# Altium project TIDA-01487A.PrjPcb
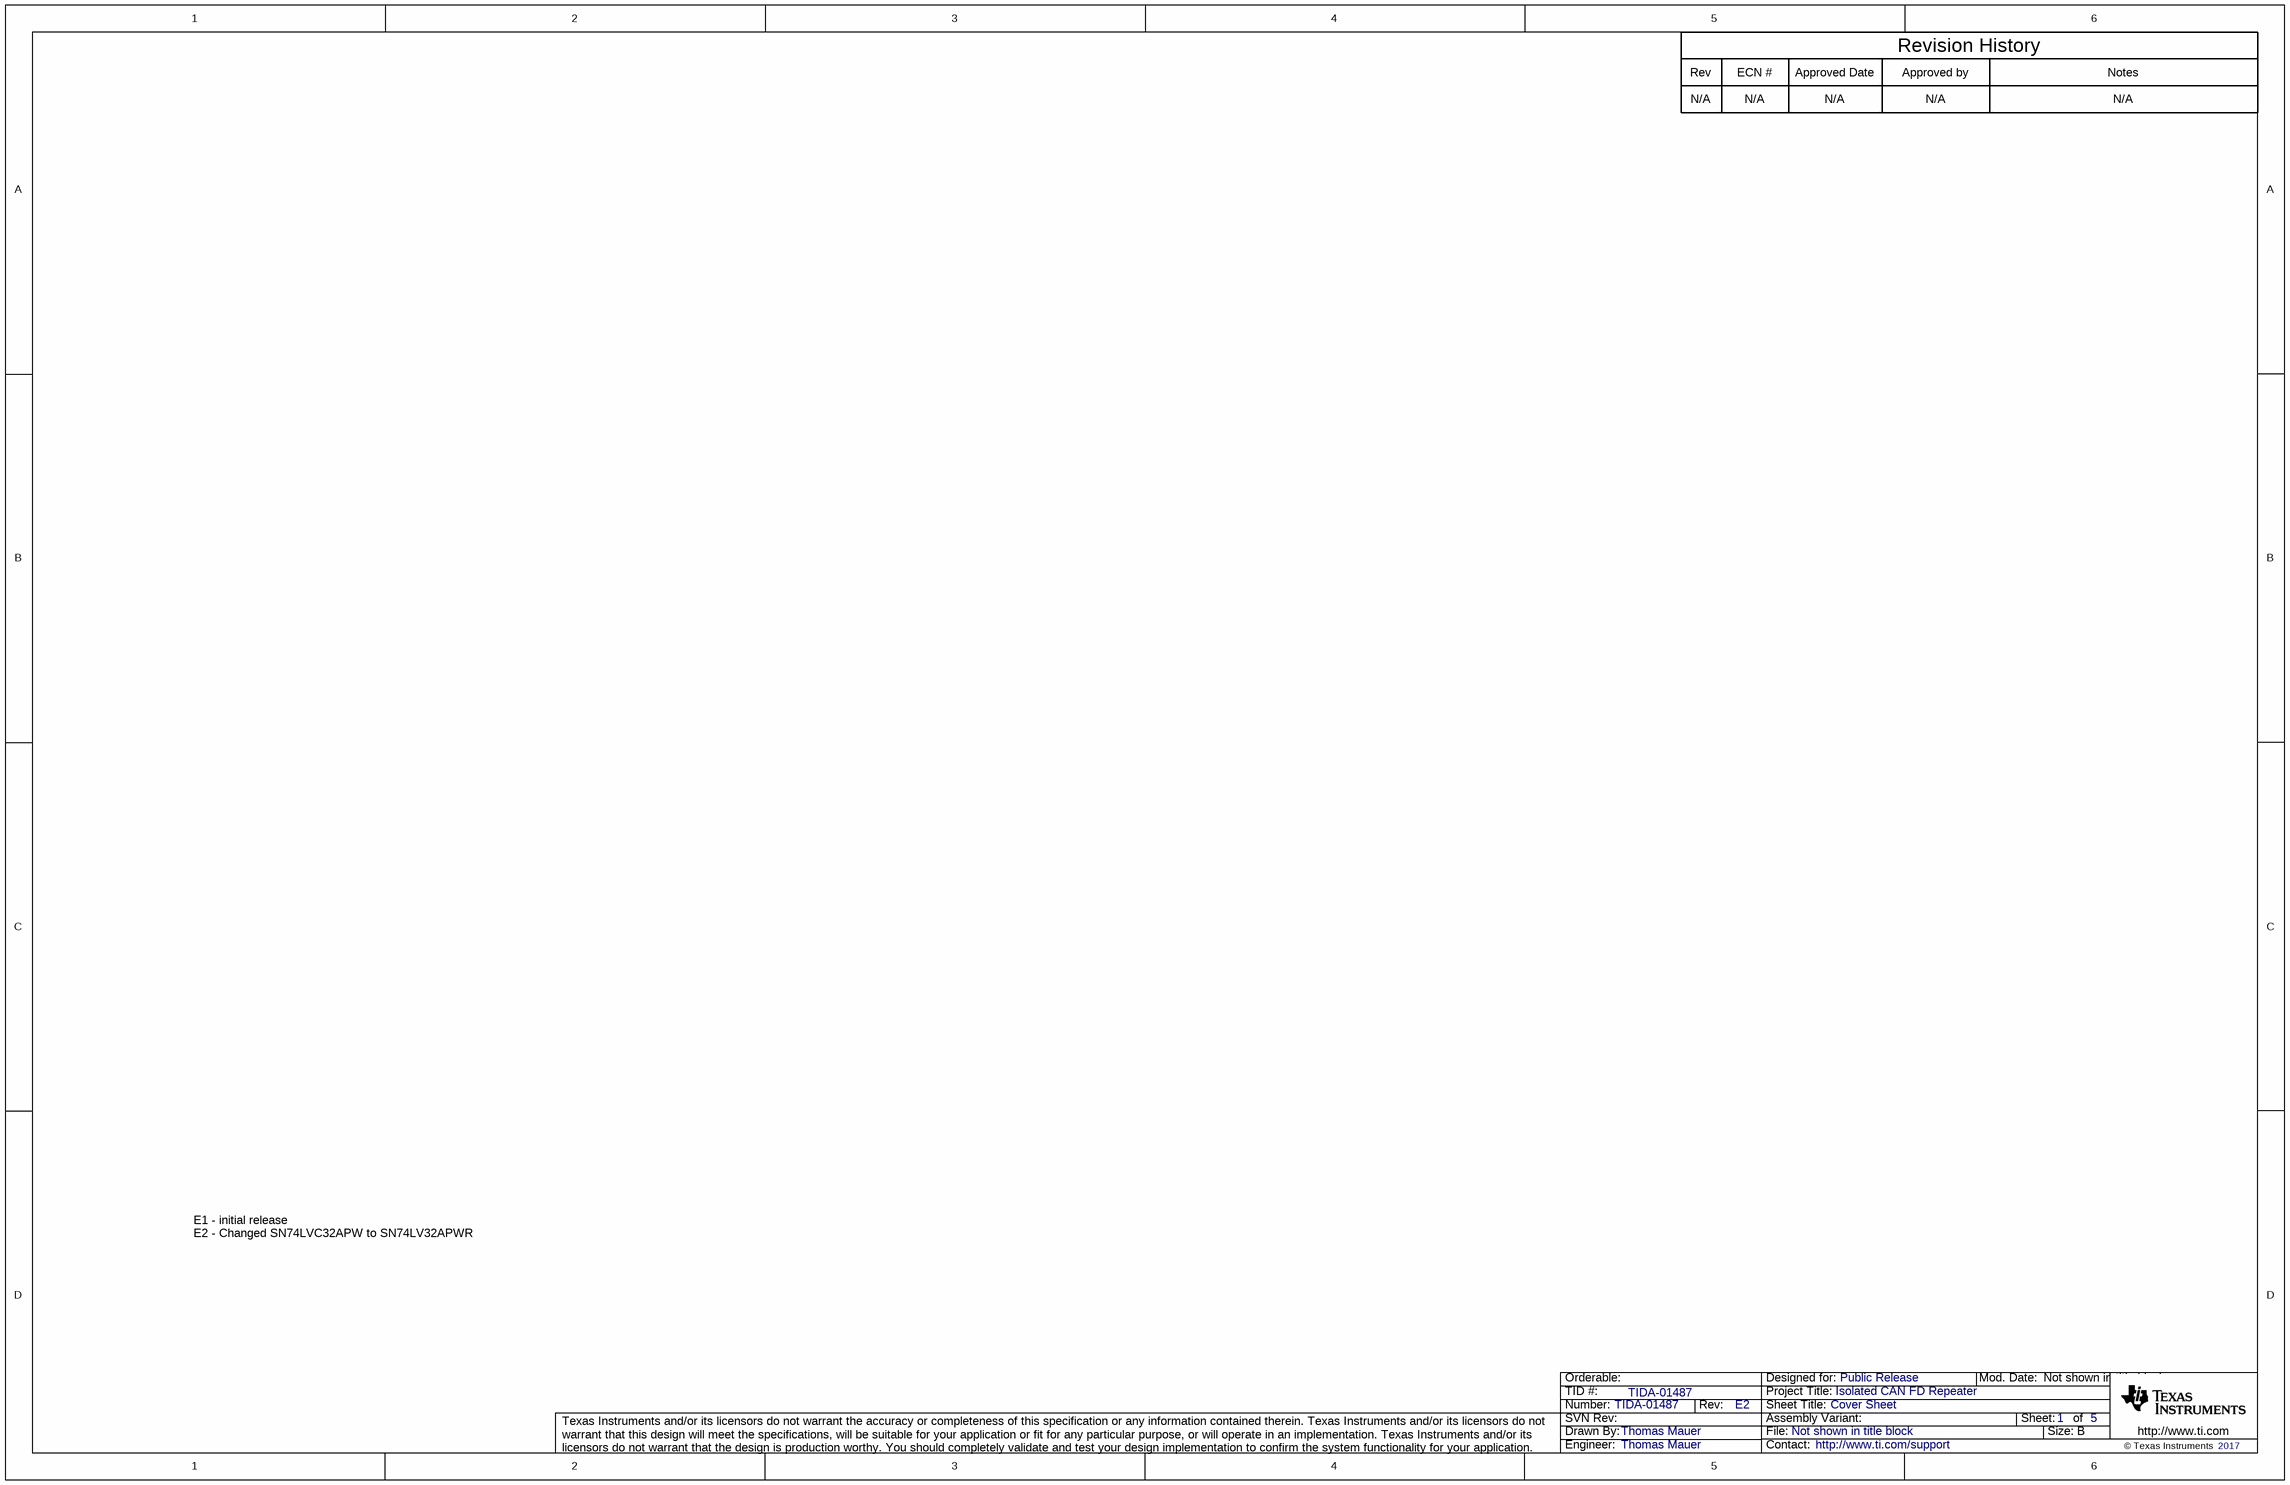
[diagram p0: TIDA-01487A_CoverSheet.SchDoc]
CopyrightYear: 2017; PCB_Layout: Thomas Mauer; PCB_Rev: E2; PRJ_Customer: Public Release; PRJ_Engineer: Thomas Mauer; PRJ_Number: TIDA-01487; PRJ_Title: Isolated CAN FD Repeater; SCH_Rev: E2; TechSupport: http://www.ti.com/support; TID: TIDA-01487
5 sheets, 83 parts. Net scope: flat (ports and power ports of the same name join across sheets).
Board file: TIDA-01487A.PcbDoc
Sheets:
  TIDA-01487A_CoverSheet.SchDoc
  TIDA-01487A_Power.SchDoc
  TIDA-01487A_BusArbitrationLogic.SchDoc
  TIDA-01487A_CanFdInterface.SchDoc
  TIDA-01487A_EVM_Hardware.SchDoc

## Sheet TIDA-01487A_CoverSheet.SchDoc: Cover Sheet
size 431 x 279 mm; Date: Not shown in title block; ApprovedBy: Not shown in title block; CheckedBy: Not shown in title block; Author: Not shown in title block; CompanyName: Not shown in title block; DrawnBy: Thomas Mauer; Engineer: Not shown in title block; Organization: Not shown in title block; Address1: Not shown in title block; Address2: Not shown in title block; Address3: Not shown in title block; Address4: Not shown in title block; DocumentNumber: 1; Revision: Use project parameter SCH_Rev; SheetNumber: 1; SheetTotal: 5; PageSetup: Record=PageOptions¦CenterHorizontal=True¦CenterVertical=True¦PrintScale=1.00¦XCorrection=1.00¦YCorrection=1.00¦PrintKind=0¦BorderSize=5000000¦LeftOffset=0¦BottomOffset=0¦Orientation=2¦PaperLength=1000¦PaperWidth=1000¦Scale=100¦PaperSource=15¦PrintQuality=600¦MediaType=1¦DitherType=10¦PaperKind=Letter¦PrintScaleMode=1

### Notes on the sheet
- Rev
- N/A
- ECN #
- Approved Date
- Approved by
- Revision History
- Notes
- E1 - initial release
  E2 - Changed SN74LVC32APW to SN74LV32APWR

## Sheet TIDA-01487A_Power.SchDoc: Power Supply
size 431 x 279 mm; Date: Not shown in title block; ApprovedBy: Not shown in title block; CheckedBy: Not shown in title block; Author: Not shown in title block; CompanyName: Not shown in title block; DrawnBy: Thomas Mauer; Engineer: Not shown in title block; Organization: Not shown in title block; Address1: Not shown in title block; Address2: Not shown in title block; Address3: Not shown in title block; Address4: Not shown in title block; DocumentNumber: 1; Revision: Use project parameter SCH_Rev; SheetNumber: 2; SheetTotal: 5; PageSetup: Record=PageOptions¦CenterHorizontal=True¦CenterVertical=True¦PrintScale=0.62¦XCorrection=1.00¦YCorrection=1.00¦PrintKind=0¦BorderSize=5000000¦LeftOffset=0¦BottomOffset=0¦Orientation=2¦PaperLength=1000¦PaperWidth=1000¦Scale=100¦PaperSource=15¦PrintQuality=600¦MediaType=1¦DitherType=10¦PrintScaleMode=1¦PaperKind=Letter
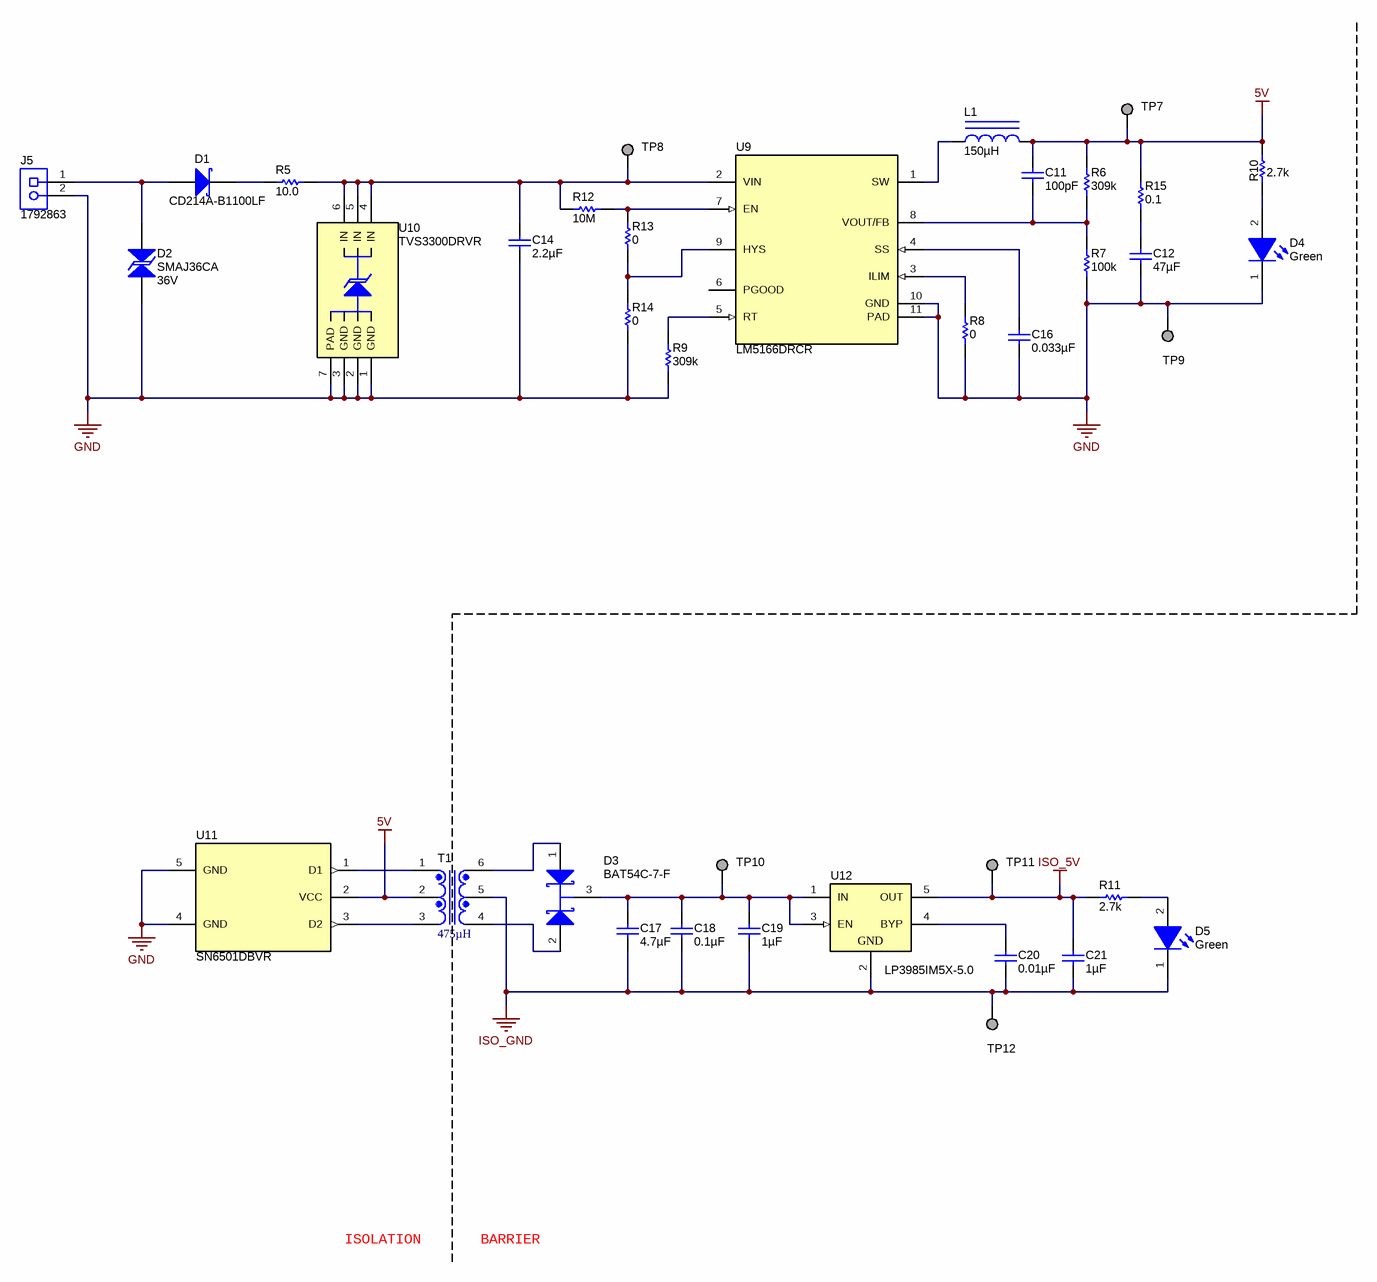
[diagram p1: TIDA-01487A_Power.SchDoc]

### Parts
C11  ValueDisplayed: 100pF  [0805_HV]  (hidden comment: GRM2165C1H101JA01D)
C12  ValueDisplayed: 47µF  [1210_270]  (hidden comment: GCM32ER70J476KE19L)
C14  ValueDisplayed: 2.2µF  [1210_270]  (hidden comment: GRM32ER72A225KA35L)
C16  ValueDisplayed: 0.033µF  [0603]  (hidden comment: GRM188R71H333KA61D)
C17  ValueDisplayed: 4.7µF  [1210_270]  (hidden comment: GRM32ER71K475KE14L)
C18  ValueDisplayed: 0.1µF  [0805_HV]  (hidden comment: ECPU1C104MA5)
C19  ValueDisplayed: 1µF  [0805_HV]  (hidden comment: EMK212B7105KG-T)
C20  ValueDisplayed: 0.01µF  [0805_HV]  (hidden comment: GRM216R71H103KA01D)
C21  ValueDisplayed: 1µF  [0805_HV]  (hidden comment: EMK212B7105KG-T)
D1  CD214A-B1100LF  [SMA]
D2  SMAJ36CA  value 36V  [SMA]
D3  BAT54C-7-F  [SOT-23]
D4  value Green  [WL-SMCW_Green_0805]  (hidden comment: 150080GS75000)
D5  value Green  [WL-SMCW_Green_0805]  (hidden comment: 150080GS75000)
J5  1792863  [Phoenix_1792863]
L1  ValueDisplayed: 150µH  [WE-PD_1050]  (hidden comment: 7447714151)
R5  ValueDisplayed: 10.0  [1206]  (hidden comment: ERJ-8ENF10R0V)
R6  ValueDisplayed: 309k  [0805_HV]  (hidden comment: CRCW0805309KFKEA)
R7  ValueDisplayed: 100k  [0805_HV]  (hidden comment: CRCW0805100KFKEA)
R8  ValueDisplayed: 0  [0805_HV]  (hidden comment: CRCW08050000Z0EA)
R9  ValueDisplayed: 309k  [0805_HV]  (hidden comment: CRCW0805309KFKEA)
R10  ValueDisplayed: 2.7k  [0805_HV]  (hidden comment: CRCW08052K70JNEA)
R11  ValueDisplayed: 2.7k  [0805_HV]  (hidden comment: CRCW08052K70JNEA)
R12  ValueDisplayed: 10M  [0805_HV]  (hidden comment: CRCW080510M0JNEA)
R13  ValueDisplayed: 0  [0805_HV]  (hidden comment: CRCW08050000Z0EA)
R14  ValueDisplayed: 0  [0805_HV]  (hidden comment: CRCW08050000Z0EA)
R15  ValueDisplayed: 0.1  [0805_HV]  (hidden comment: CRM0805-FX-R100ELF)
T1  ValueDisplayed: 475µH  [Wurth_760390013]  (hidden comment: 760390014)
TP7  TESTPOINT  [TESTPOINT]  (value not drawn)  (no BOM)
TP8  TESTPOINT  [TESTPOINT]  (value not drawn)  (no BOM)
TP9  TESTPOINT  [TESTPOINT]  (value not drawn)  (no BOM)
TP10  TESTPOINT  [TESTPOINT]  (value not drawn)  (no BOM)
TP11  TESTPOINT  [TESTPOINT]  (value not drawn)  (no BOM)
TP12  TESTPOINT  [TESTPOINT]  (value not drawn)  (no BOM)
U9  LM5166DRCR  [DRC0010J]
U10  TVS3300DRVR  [DRV0006A]
U11  SN6501DBVR  [DBV0005A_N]
U12  LP3985IM5X-5.0  [MF05A_N]

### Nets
5V: C11.1 L1.2 R6.2 R10.2 R15.2 T1.2 TP7.1 U11.2(VCC)
GND: C12.2 C14.2 C16.2 D2.1 D4.1(K) J5.2 R7.1 R8.1 R9.1 R14.1 TP9.1 U9.10(GND) U9.11(PAD) U10.1(GND) U10.2(GND) U10.3(GND) U10.7(PAD) U11.4(GND) U11.5(GND)
ISO_5V: C21.1 R11.2 TP11.1 U12.5(OUT)
ISO_GND: C17.2 C18.2 C19.2 C20.2 C21.2 D5.1(K) T1.5 TP12.1 U12.2(GND)
NetC11_2: C11.2 R6.1 R7.2 U9.8(VOUT/FB)
NetC12_1: C12.1 R15.1
NetC14_1: C14.1 R5.2 R12.1 TP8.1 U9.2(VIN) U10.4(IN) U10.5(IN) U10.6(IN)
NetC16_1: C16.1 U9.4(SS)
NetC17_1: C17.1 C18.1 C19.1 D3.3(K) TP10.1 U12.1(IN) U12.3(EN)
NetC20_1: C20.1 U12.4(BYP)
NetD1_1: D1.1(K) R5.1
NetD1_2: D1.2(A) D2.2 J5.1
NetD3_1: D3.1(A1) T1.6
NetD3_2: D3.2(A2) T1.4
NetD4_2: D4.2(A) R10.1
NetD5_2: D5.2(A) R11.1
NetL1_1: L1.1 U9.1(SW)
NetR8_2: R8.2 U9.3(ILIM)
NetR9_2: R9.2 U9.5(RT)
NetR12_2: R12.2 R13.2 U9.7(EN)
NetR13_1: R13.1 R14.2 U9.9(HYS)
NetT1_1: T1.1 U11.1(D1)
NetT1_3: T1.3 U11.3(D2)

Not connected (* = marked no-connect by the designer): U9 6(PGOOD)

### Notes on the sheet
- ISOLATION       BARRIER

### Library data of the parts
C11 = GRM2165C1H101JA01D: CAP, CERM, 100 pF, 50 V,+/- 5%, C0G/NP0, 0805; Manufacturer: MuRata; Polarized: N; CompType: Capacitor; Value: 100pF; U/M: EA; Cap_F: 0.0000000001; Tolerance_%: 5; VDC_V: 50; Value2: 50V; TaMin_C: -55; TaMax_C: 125; Cap_Case: 0805; SizeArea_mm2: 2.5; SizeAreaWB_mm2: 6.75; SizeX_mm: 2; SizeY_mm: 1.25; SizeZ_mm: 1.45; AEC Category: Q200; Green_Lifecycle: Active; Green_REACh: Passed
C12 = GCM32ER70J476KE19L: CAP, CERM, 47 µF, 6.3 V,+/- 10%, X7R, AEC-Q200 Grade 1, 1210; Manufacturer: MuRata; Polarized: N; CompType: Capacitor; Value: 47uF; U/M: EA; Cap_F: 0.000047; Tolerance_%: 10; VDC_V: 6.3; Value2: 6.3V; TaMin_C: -55; TaMax_C: 125; Cap_Case: 1210; SizeArea_mm2: 8; SizeAreaWB_mm2: 14.7; SizeX_mm: 3.2; SizeY_mm: 2.5; SizeZ_mm: 2.7; AEC Category: Q200; AEC Qualified: Y; AEC Grade: 1; Green_Lifecycle: Active; Green_REACh: Passed
C14 = GRM32ER72A225KA35L: CAP, CERM, 2.2 µF, 100 V,+/- 10%, X7R, 1210; Manufacturer: MuRata; Polarized: N; CompType: Capacitor; Value: 2.2uF; U/M: EA; Cap_F: 0.0000022; Tolerance_%: 10; ESR_ohm: 0.007; Value1: 0.007 ohm; VDC_V: 100; Value2: 100V; IRMS_A: 4.4; TaMin_C: -55; TaMax_C: 125; Cap_Case: 1210; SizeArea_mm2: 8; SizeAreaWB_mm2: 14.7; SizeX_mm: 3.2; SizeY_mm: 2.5; SizeZ_mm: 2.7; AEC Category: Q200; Green_Lifecycle: Active; Green_REACh: Passed
C16 = GRM188R71H333KA61D: CAP, CERM, 0.033 µF, 50 V,+/- 10%, X7R, 0603; Manufacturer: MuRata; Polarized: N; CompType: Capacitor; Value: 0.033uF; U/M: EA; Cap_F: 0.000000033; Tolerance_%: 10; VDC_V: 50; Value2: 50V; TaMin_C: -55; TaMax_C: 125; SizeArea_mm2: 1.28; SizeAreaWB_mm2: 4.68; SizeX_mm: 1.6; SizeY_mm: 0.8; SizeZ_mm: 1; AEC Category: Q200; Green_Lifecycle: Active; Green_REACh: Passed
C17 = GRM32ER71K475KE14L: CAP, CERM, 4.7 µF, 80 V,+/- 10%, X7R, 1210; Manufacturer: MuRata; Polarized: N; CompType: Capacitor; Value: 4.7uF; U/M: EA; Cap_F: 0.0000047; Tolerance_%: 10; VDC_V: 80; Value2: 80V; TaMin_C: -55; TaMax_C: 125; Cap_Case: 1210; SizeArea_mm2: 8; SizeAreaWB_mm2: 14.7; SizeX_mm: 3.2; SizeY_mm: 2.5; SizeZ_mm: 2.7; AEC Category: Q200
C18 = ECPU1C104MA5: CAP, Film, 0.1 µF, 16 V,+/- 20%, 0805 SMD; Manufacturer: Panasonic; Polarized: N; CompType: Capacitor; Value: 0.1uF; U/M: EA; Cap_F: 0.0000001; Tolerance_%: 20; VDC_V: 16; Value2: 16V; TaMin_C: -40; TaMax_C: 85; Cap_Case: 0805; SizeAreaWB_mm2: 6.75; SizeArea_mm2: 2.5; SizeX_mm: 2; SizeY_mm: 1.25; SizeZ_mm: 1.45; AEC Category: Q200
C19 C21 = EMK212B7105KG-T: CAP, CERM, 1 µF, 16 V,+/- 10%, X7R, 0805; Manufacturer: Taiyo Yuden; Polarized: N; CompType: Capacitor; Value: 1uF; U/M: EA; Cap_F: 0.000001; Tolerance_%: 10; VDC_V: 16; Value2: 16V; TaMin_C: -55; TaMax_C: 125; Cap_Case: 0805; SizeArea_mm2: 2.5; SizeAreaWB_mm2: 6.75; SizeX_mm: 2; SizeY_mm: 1.25; SizeZ_mm: 1.45; AEC Category: Q200; Green_Lifecycle: Active; Green_REACh: Passed
C20 = GRM216R71H103KA01D: CAP, CERM, 0.01 µF, 50 V,+/- 10%, X7R, 0805; Manufacturer: MuRata; Polarized: N; CompType: Capacitor; Value: 0.01uF; U/M: EA; Cap_F: 0.00000001; Tolerance_%: 10; VDC_V: 50; Value2: 50V; TaMin_C: -55; TaMax_C: 125; Cap_Case: 0805; SizeArea_mm2: 2.5; SizeAreaWB_mm2: 6.75; SizeX_mm: 2; SizeY_mm: 1.25; SizeZ_mm: 1.45; AEC Category: Q200; Green_Lifecycle: Active; Green_REACh: Passed
D1 = CD214A-B1100LF: Diode, Schottky, 100 V, 1 A, SMA; Manufacturer: Bourns; U/M: EA; Vf_V: 0.79; Value: 100V; Value1: 1A; Value2: 0.79V; Io_A: 1; Vr_V: 100; TJmax_C: 125; RJC_CperW: 25; SizeAreaWB_mm2: 37.3428; SizeArea_mm2: 16.3228; SizeX_mm: 5.59; SizeY_mm: 2.92; SizeZ_mm: 2.87; AEC Category: Q101; Green_Lifecycle: Not Set; Green_REACh: Incomplete
D2 = SMAJ36CA: Diode, TVS, Bi, 36 V, SMA; Manufacturer: Littelfuse; U/M: EA; Power_W: 3.3; Vr_V: 36; Value1: 3.3W; RJA_CperW: 120; SizeAreaWB_mm2: 37.3428; SizeArea_mm2: 16.3228; SizeX_mm: 5.59; SizeY_mm: 2.92; SizeZ_mm: 2.87; AEC Category: Q101
D3 = BAT54C-7-F: Diode, Schottky, 30 V, 0.2 A, SOT-23; Manufacturer: Diodes Inc.; Value: 30V; U/M: EA; Vf_V: 0.65; Value1: 0.2A; Value2: 0.65V; Io_A: 0.2; Vr_V: 30; TJmax_C: 125; SizeAreaWB_mm2: 14; SizeArea_mm2: 7.5; SizeX_mm: 2.5; SizeY_mm: 3; SizeZ_mm: 1.1; AEC Category: Q101; Green_Lifecycle: Active; Green_REACh: Passed
D4 D5 = 150080GS75000: LED, Green, SMD; Manufacturer: Wurth Elektronik; Type: InGaN; Vf_V: 3.2; Value2: 3.2V; Io_A: 0.02; Vr_V: 5; Ir_A: 1e-005; Tjmax_C: 85; Power_TotalModule: 0.105; Value1: 0.105W; Angle: 140; U/M: EA
J5 = 1792863: Terminal Block, 5mm, 2x1, R/A, TH; Manufacturer: Phoenix Contact; SymbolCreator: a0412235; Pitch_mm: 5; Gender: Female; Row_Count: 1; Current_A: 16; Voltage_V: 400; Cert_UL: Y
L1 = 7447714151: Inductor, Shielded Drum Core, Ferrite, 150 µH, 1.2 A, 0.251 ohm, SMD; Manufacturer: Wurth Elektronik; Value: 150uH; Ind_H: 150.0E-6; Imax_A: 1.2; Irms: 1.2A @ 40C rise; Isat: 1.4A @ 10% inductance drop; DCR_ohm: 0.251; Value2: 1.2A; SizeAreaWB_mm2: 144; SizeArea_mm2: 100; SizeX_mm: 10; SizeZ_mm: 5; AEC Category: Q200; Green_Lifecycle: Active; Green_REACh: Passed
R5 = ERJ-8ENF10R0V: RES, 10.0, 1%, 0.25 W, 1206; Manufacturer: Panasonic; CompType: Resistor; Value: 10.0; Res_ohm: 10; Value_Code: 10R0; Tolerance_%: 1; Power_W: 0.25; Value2: 0.25W; VDC_V: 200; TempCo: 100 ppm/C; SizeArea_mm2: 5.12; SizeX_mm: 3.2; SizeY_mm: 1.6; SizeZ_mm: 1.35; EIA_Code: E96; U/M: EA; AEC Category: Q200; Green_Lifecycle: Active; Green_REACh: Passed
R6 R9 = CRCW0805309KFKEA: RES, 309 k, 1%, 0.125 W, 0805; Manufacturer: Vishay-Dale; CompType: Resistor; Value: 309k; Res_ohm: 309000; Tolerance_%: 1; Power_W: 0.125; Value2: 0.125W; VDC_V: 150; TempCo: 100 ppm/C; SizeArea_mm2: 2.5; SizeX_mm: 2; SizeY_mm: 1.25; SizeZ_mm: 1.45; EIA_Code: E96; U/M: EA; AEC Category: Q200
R7 = CRCW0805100KFKEA: RES, 100 k, 1%, 0.125 W, 0805; Manufacturer: Vishay-Dale; CompType: Resistor; Value: 100k; Res_ohm: 100000; Tolerance_%: 1; Power_W: 0.125; Value2: 0.125W; VDC_V: 150; TempCo: 100 ppm/C; SizeArea_mm2: 2.5; SizeX_mm: 2; SizeY_mm: 1.25; SizeZ_mm: 1.45; EIA_Code: E96; U/M: EA; AEC Category: Q200; Green_Lifecycle: Active; Green_REACh: Passed
R8 R13 R14 = CRCW08050000Z0EA: RES, 0, 5%, 0.125 W, 0805; Manufacturer: Vishay-Dale; CompType: Resistor; Value: 0; Value_Code: 0000; Tolerance_%: 5; Power_W: 0.125; Value2: 0.125W; VDC_V: 150; TempCo: 200 ppm/C; SizeArea_mm2: 2.5; SizeX_mm: 2; SizeY_mm: 1.25; SizeZ_mm: 1.45; EIA_Code: E24; U/M: EA; AEC Category: Q200; Green_Lifecycle: Active; Green_REACh: Passed
R10 R11 = CRCW08052K70JNEA: RES, 2.7 k, 5%, 0.125 W, 0805; Manufacturer: Vishay-Dale; CompType: Resistor; Value: 2.7k; Res_ohm: 2700; Value_Code: 2k70; Tolerance_%: 5; Power_W: 0.125; Value2: 0.125W; VDC_V: 150; TempCo: 200 ppm/C; SizeArea_mm2: 2.5; SizeX_mm: 2; SizeY_mm: 1.25; SizeZ_mm: 1.45; EIA_Code: E24; U/M: EA; AEC Category: Q200
R12 = CRCW080510M0JNEA: RES, 10 M, 5%, 0.125 W, 0805; Manufacturer: Vishay-Dale; CompType: Resistor; Value: 10Meg; Res_ohm: 10000000; Value_Code: 10M0; Tolerance_%: 5; Power_W: 0.125; Value2: 0.125W; VDC_V: 150; TempCo: 200 ppm/C; SizeArea_mm2: 2.5; SizeX_mm: 2; SizeY_mm: 1.25; SizeZ_mm: 1.45; EIA_Code: E24; U/M: EA; AEC Category: Q200
R15 = CRM0805-FX-R100ELF: RES, 0.1, 1%, 0.25 W, 0805; Manufacturer: Bourns; CompType: Resistor; Value: 0.1; Value_Code: R100; Tolerance_%: 1; Power_W: 0.25; Value2: 0.25W; VDC_V: 0; TempCo: 150 ppm/C; SizeArea_mm2: 2.5; SizeX_mm: 2; SizeY_mm: 1.25; SizeZ_mm: 1.45; EIA_Code: E96; U/M: EA; AEC Category: Q200; Green_Lifecycle: Active; Green_REACh: Passed
T1 = 760390014: Transformer, 475uH, SMT; Manufacturer: Wurth Elektronik; SymbolCreator: a0799628; DCR_ohm: 0.31; Lp: 475; Ind_H: 0.000475
TP7-TP12 = TESTPOINT: TEST POINT.  No entry in BOM.
U9 = LM5166DRCR: 3V-65V Input, 500mA Synchronous Buck Converter With Ultra-Low Iq, DRC0010J (VSON-10); Alternate PartNumber: LM5166DRCT; Manufacturer: Texas Instruments; SymbolCreator: a0411947; SizeArea_mm2: 9; SizeAreaWB_mm2: 16; SizeX_mm: 3; SizeZ_mm: 1; CompType: IC; U/M: EA
U10 = TVS3300DRVR: 33V Precision Surge Protection Clamp, DRV0006A (WSON-6); Alternate PartNumber: TVS3300DRVT; Manufacturer: Texas Instruments; SymbolCreator: Altium; SizeArea_mm2: 4; SizeAreaWB_mm2: 9; SizeX_mm: 2; SizeZ_mm: 0.8; CompType: IC; U/M: EA
U11 = SN6501DBVR: Low-Noise 350 mA, 410 kHz Transformer Driver, DBV0005A (SOT-23-5); Alternate PartNumber: SN6501DBVT; Manufacturer: Texas Instruments; SymbolCreator: a0411947; SizeArea_mm2: 8.12; SizeAreaWB_mm2: 14.82; SizeX_mm: 2.8; SizeY_mm: 2.9; SizeZ_mm: 1.45; CompType: IC; U/M: EA; Green_Lifecycle: Not Set; Green_REACh: Passed
U12 = LP3985IM5X-5.0: Micropower, 150mA Low-Noise Ultra Low-Dropout CMOS Voltage Regulator, 5-pin SOT-23; Manufacturer: Texas Instruments; PackageTopMarking: LDSB*XTT; PowerWise: N; CompType: LDO IC

## Sheet TIDA-01487A_BusArbitrationLogic.SchDoc: Bus Arbitration Logic
size 431 x 279 mm; Date: Not shown in title block; ApprovedBy: Not shown in title block; CheckedBy: Not shown in title block; Author: Not shown in title block; CompanyName: Not shown in title block; DrawnBy: Thomas Mauer; Engineer: Not shown in title block; Organization: Not shown in title block; Address1: Not shown in title block; Address2: Not shown in title block; Address3: Not shown in title block; Address4: Not shown in title block; DocumentNumber: 1; Revision: Use project parameter SCH_Rev; SheetNumber: 3; SheetTotal: 5; PageSetup: Record=PageOptions¦CenterHorizontal=True¦CenterVertical=True¦PrintScale=0.62¦XCorrection=1.00¦YCorrection=1.00¦PrintKind=0¦BorderSize=5000000¦LeftOffset=0¦BottomOffset=0¦Orientation=2¦PaperLength=1000¦PaperWidth=1000¦Scale=100¦PaperSource=15¦PrintQuality=600¦MediaType=1¦DitherType=10¦PrintScaleMode=1¦PaperKind=Letter
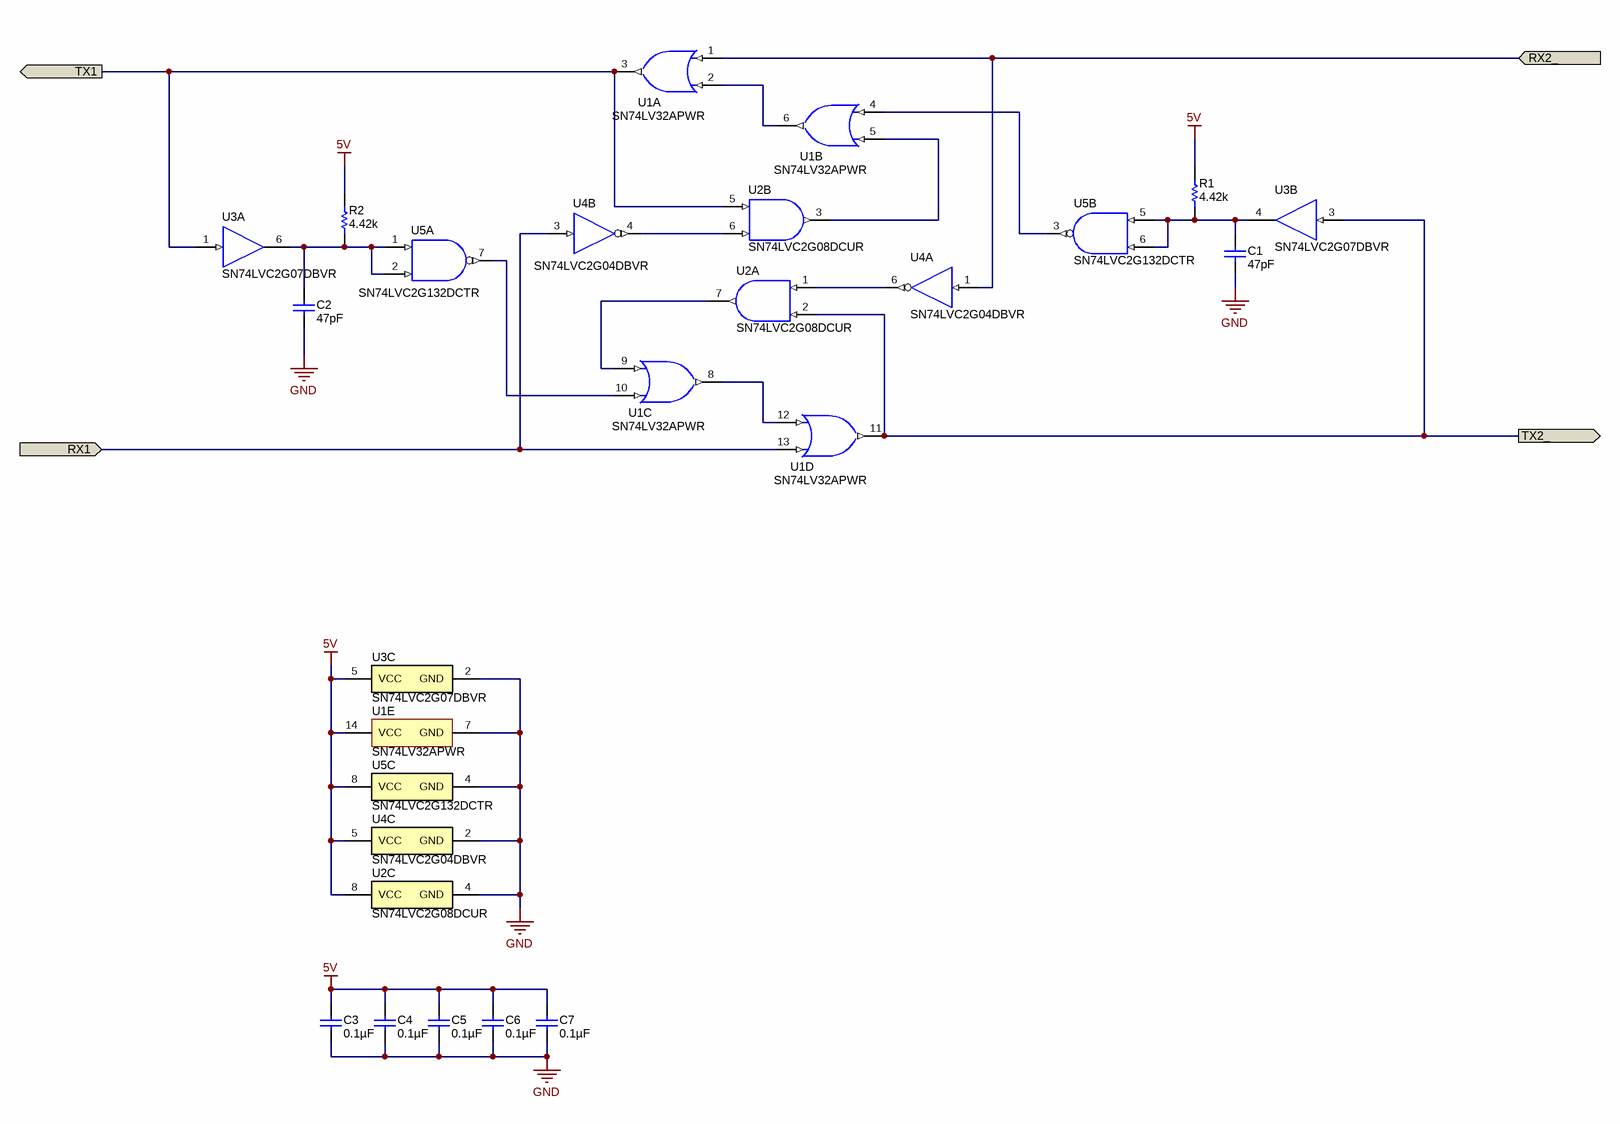
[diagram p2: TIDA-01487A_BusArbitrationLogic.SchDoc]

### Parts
C1  ValueDisplayed: 47pF  [0805_HV]  (hidden comment: GQM2195C1H470JB01D)
C2  ValueDisplayed: 47pF  [0805_HV]  (hidden comment: GQM2195C1H470JB01D)
C3  ValueDisplayed: 0.1µF  [0805_HV]  (hidden comment: ECPU1C104MA5)
C4  ValueDisplayed: 0.1µF  [0805_HV]  (hidden comment: ECPU1C104MA5)
C5  ValueDisplayed: 0.1µF  [0805_HV]  (hidden comment: ECPU1C104MA5)
C6  ValueDisplayed: 0.1µF  [0805_HV]  (hidden comment: ECPU1C104MA5)
C7  ValueDisplayed: 0.1µF  [0805_HV]  (hidden comment: ECPU1C104MA5)
R1  ValueDisplayed: 4.42k  [0805_HV]  (hidden comment: CRCW08054K42FKEA)
R2  ValueDisplayed: 4.42k  [0805_HV]  (hidden comment: CRCW08054K42FKEA)
U1  SN74LV32APWR  [PW0014A_N]  (parts A,B,C,D,E of 5)
U2  SN74LVC2G08DCUR  [DCU0008A_N]  (parts A,B,C of 3)
U3  SN74LVC2G07DBVR  [DBV0006A_N]  (parts A,B,C of 3)
U4  SN74LVC2G04DBVR  [DBV0006A_N]  (parts A,B,C of 3)
U5  SN74LVC2G132DCTR  [DCT0008A_N]  (parts A,B,C of 3)

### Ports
RX1 (in), RX2_ (in), TX1 (out), TX2_ (out)

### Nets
5V: C3.1 C4.1 C5.1 C6.1 C7.1 R1.2 R2.2 U1.14(VCC) U2.8(VCC) U3.5(VCC) U4.5(VCC) U5.8(VCC)
GND: C1.1 C2.1 C3.2 C4.2 C5.2 C6.2 C7.2 U1.7(GND) U2.4(GND) U3.2(GND) U4.2(GND) U5.4(GND)
RX1: U1.13(4B) U4.3(2A) ; port RX1
RX2_: U1.1(1A) U4.1(1A) ; port RX2_
TX1: U1.3(1Y) U2.5(2A) U3.1(1A) ; port TX1
TX2_: U1.11(4Y) U2.2(1B) U3.3(2A) ; port TX2_
NetC1_2: C1.2 R1.1 U3.4(2Y) U5.5(2A) U5.6(2B)
NetC2_2: C2.2 R2.1 U3.6(1Y) U5.1(1A) U5.2(1B)
NetU1_2: U1.2(1B) U1.6(2Y)
NetU1_4: U1.4(2A) U5.3(2Y)
NetU1_5: U1.5(2B) U2.3(2Y)
NetU1_8: U1.8(3Y) U1.12(4A)
NetU1_9: U1.9(3A) U2.7(1Y)
NetU1_10: U1.10(3B) U5.7(1Y)
NetU2_1: U2.1(1A) U4.6(1Y)
NetU2_6: U2.6(2B) U4.4(2Y)

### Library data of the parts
C1 C2 = GQM2195C1H470JB01D: CAP, CERM, 47 pF, 50 V,+/- 5%, C0G/NP0, 0805; Manufacturer: MuRata; Polarized: N; CompType: Capacitor; Value: 47pF; U/M: EA; Cap_F: 0.000000000047; Tolerance_%: 5; VDC_V: 50; Value2: 50V; TaMin_C: -55; TaMax_C: 125; Cap_Case: 0805; SizeArea_mm2: 2.5; SizeAreaWB_mm2: 6.75; SizeX_mm: 2; SizeY_mm: 1.25; SizeZ_mm: 1.45; AEC Category: Q200
C3-C7 = ECPU1C104MA5: as C18 on sheet TIDA-01487A_Power
R1 R2 = CRCW08054K42FKEA: RES, 4.42 k, 1%, 0.125 W, 0805; Manufacturer: Vishay-Dale; CompType: Resistor; Value: 4.42k; Res_ohm: 4420; Value_Code: 4k42; Tolerance_%: 1; Power_W: 0.125; Value2: 0.125W; VDC_V: 150; TempCo: 100 ppm/C; SizeArea_mm2: 2.5; SizeX_mm: 2; SizeY_mm: 1.25; SizeZ_mm: 1.45; EIA_Code: E96; U/M: EA; AEC Category: Q200
U1 = CMP-0050867-1: Quadruple 2-Input Positive-OR Gates, PW0014A, LARGE T&R; Manufacturer: Texas Instruments; ICC @ Nom Voltage(Max)(mA): 0.02; Input Type: TTL; VCC(Max)(V): 5.5; VCC(Min)(V): 2; F @ Nom Voltage(Max)(Mhz): 70; Rating: Catalog; Output Drive (IOL/IOH)(Max)(mA): 50/-50; Bits(#): 4; Voltage(Nom)(V): 2.5,3.3,5; tpd @ Nom Voltage(Max)(ns): 19,13,8.5
U2 = SN74LVC2G08DCUR: Dual 2-Input Positive-AND Gate, DCU0008A, LARGE T&R; Manufacturer: Texas Instruments; Alternate PartNumber: Equivalent; VCC(Min)(V): 1.65; VCC(Max)(V): 5.5; Output Type: CMOS; ICC @ Nom Voltage(Max)(mA): 0.01; Input Type: CMOS/TTL; Bits(#): 2; F @ Nom Voltage(Max)(Mhz): 150; Rating: Catalog; Technology Family: LVC; Voltage(Nom)(V): 1.8,2.5,3.3,5; Schmitt Trigger: No; Output Drive (IOL/IOH)(Max)(mA): 32/-32; tpd @ Nom Voltage(Max)(ns): 9.8,5.8,5.3,4.8; Logic: True; Gate Type: AND
U3 = SN74LVC2G07DBVR: Dual Buffer/Driver with Open-Drain Output, DBV0006A, LARGE T&R; Manufacturer: Texas Instruments; Alternate PartNumber: Equivalent; VCC(Min)(V): 1.65; VCC(Max)(V): 5.5; Output Type: CMOS; ICC @ Nom Voltage(Max)(mA): 0.01; Input Type: CMOS/TTL; Bits(#): 2; F @ Nom Voltage(Max)(Mhz): 150; Rating: Catalog; Technology Family: LVC; Voltage(Nom)(V): 1.8,2.5,3.3,5; Schmitt Trigger: No; Output Drive (IOL/IOH)(Max)(mA): 32/-32; tpd @ Nom Voltage(Max)(ns): 8.6,4.4,3.7,2.9; Logic: True; Sub-Family: Inverting Buffer/Driver
U4 = SN74LVC2G04DBVR: Dual Inverter, DBV0006A, LARGE T&R; Manufacturer: Texas Instruments; Alternate PartNumber: Equivalent; VCC(Min)(V): 1.65; VCC(Max)(V): 5.5; Output Type: CMOS; ICC @ Nom Voltage(Max)(mA): 0.01; Input Type: CMOS/TTL; Bits(#): 2; F @ Nom Voltage(Max)(Mhz): 150; Rating: Catalog; Technology Family: LVC; Voltage(Nom)(V): 1.8,2.5,3.3,5; Schmitt Trigger: No; Output Drive (IOL/IOH)(Max)(mA): 32/-32; tpd @ Nom Voltage(Max)(ns): 8,4.9,4.6,3.7; Logic: Inverting; Sub-Family: Inverting Buffer/Driver
U5 = SN74LVC2G132DCTR: Dual 2-Input NAND Gate with Schmitt-Trigger Inputs, DCT0008A, LARGE T&R; Manufacturer: Texas Instruments; Alternate PartNumber: Equivalent; VCC(Min)(V): 1.65; VCC(Max)(V): 5.5; Output Type: CMOS; ICC @ Nom Voltage(Max)(mA): 0.01; Input Type: CMOS/TTL; Bits(#): 2; F @ Nom Voltage(Max)(Mhz): 150; Rating: Catalog; Technology Family: LVC; Voltage(Nom)(V): 1.8,2.5,3.3,5; Schmitt Trigger: Yes; Output Drive (IOL/IOH)(Max)(mA): 32/-32; tpd @ Nom Voltage(Max)(ns): 16,7.5,6,5; Logic: True; 3-State Output: No

## Sheet TIDA-01487A_CanFdInterface.SchDoc: Bus Arbitration Logic
size 431 x 279 mm; Date: Not shown in title block; ApprovedBy: Not shown in title block; CheckedBy: Not shown in title block; Author: Not shown in title block; CompanyName: Not shown in title block; DrawnBy: Thomas Mauer; Engineer: Not shown in title block; Organization: Not shown in title block; Address1: Not shown in title block; Address2: Not shown in title block; Address3: Not shown in title block; Address4: Not shown in title block; DocumentNumber: 1; Revision: Use project parameter SCH_Rev; SheetNumber: 4; SheetTotal: 5; PageSetup: Record=PageOptions¦CenterHorizontal=True¦CenterVertical=True¦PrintScale=0.62¦XCorrection=1.00¦YCorrection=1.00¦PrintKind=0¦BorderSize=5000000¦LeftOffset=0¦BottomOffset=0¦Orientation=2¦PaperLength=1000¦PaperWidth=1000¦Scale=100¦PaperSource=15¦PrintQuality=600¦MediaType=1¦DitherType=10¦PrintScaleMode=1¦PaperKind=Letter
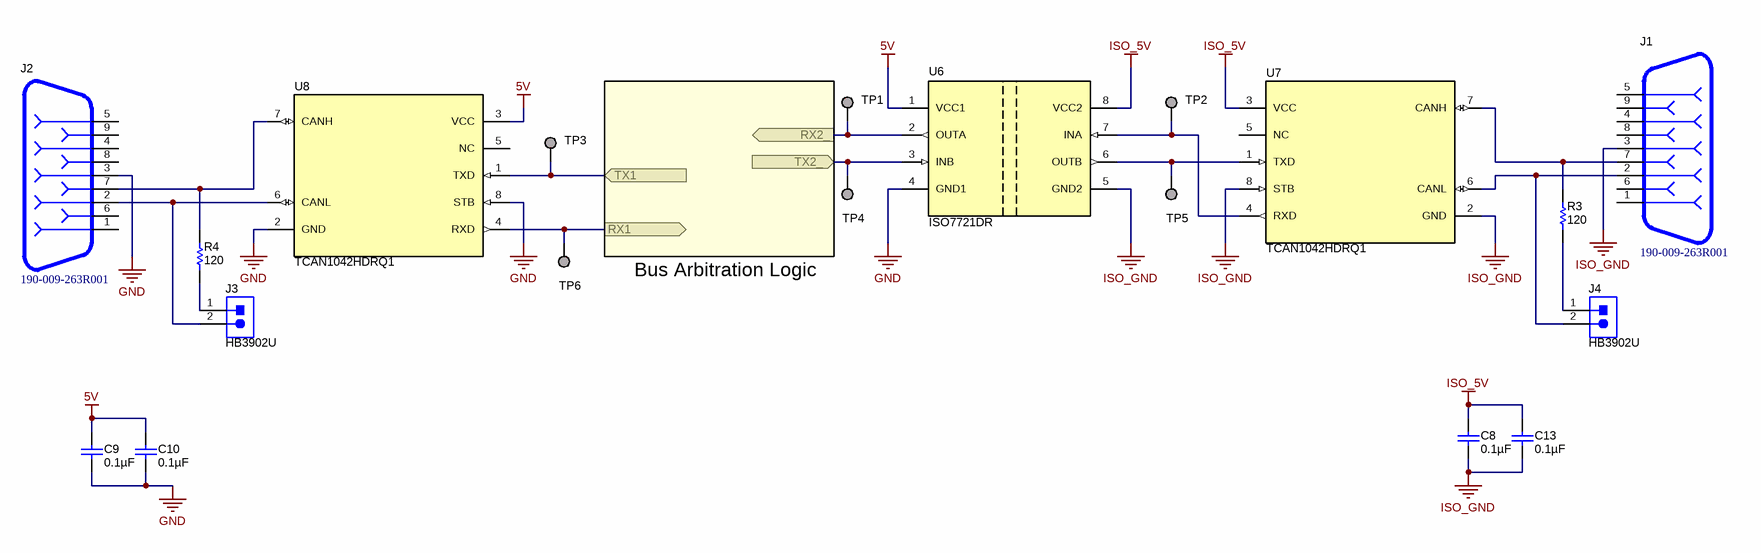
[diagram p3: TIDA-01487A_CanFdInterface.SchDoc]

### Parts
C8  ValueDisplayed: 0.1µF  [0805_HV]  (hidden comment: ECPU1C104MA5)
C9  ValueDisplayed: 0.1µF  [0805_HV]  (hidden comment: ECPU1C104MA5)
C10  ValueDisplayed: 0.1µF  [0805_HV]  (hidden comment: ECPU1C104MA5)
C13  ValueDisplayed: 0.1µF  [0805_HV]  (hidden comment: ECPU1C104MA5)
J1  190-009-263R001  [NORCOMP_190-009-263R001]
J2  190-009-263R001  [NORCOMP_190-009-263R001]
J3  HB3902U  [Foxconn_HB3902U]
J4  HB3902U  [Foxconn_HB3902U]
R3  ValueDisplayed: 120  [0805_HV]  (hidden comment: CRCW0805120RJNEA)
R4  ValueDisplayed: 120  [0805_HV]  (hidden comment: CRCW0805120RJNEA)
TP1  TESTPOINT  [TESTPOINT]  (value not drawn)  (no BOM)
TP2  TESTPOINT  [TESTPOINT]  (value not drawn)  (no BOM)
TP3  TESTPOINT  [TESTPOINT]  (value not drawn)  (no BOM)
TP4  TESTPOINT  [TESTPOINT]  (value not drawn)  (no BOM)
TP5  TESTPOINT  [TESTPOINT]  (value not drawn)  (no BOM)
TP6  TESTPOINT  [TESTPOINT]  (value not drawn)  (no BOM)
U6  ISO7721DR  [D0008B_HV]
U7  TCAN1042HDRQ1  [D0008A_N]
U8  TCAN1042HDRQ1  [D0008A_N]

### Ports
RX1 (out), RX2_ (out), TX1 (in), TX2_ (in)

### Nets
5V: C9.1 C10.1 U6.1(VCC1) U8.3(VCC)
GND: C9.2 C10.2 J2.3 U6.4(GND1) U8.2(GND) U8.8(STB)
ISO_5V: C8.1 C13.1 U6.8(VCC2) U7.3(VCC)
ISO_GND: C8.2 C13.2 J1.3 U6.5(GND2) U7.2(GND) U7.8(STB)
RX1: TP6.1 U8.4(RXD) ; port RX1
RX2_: TP1.1 U6.2(OUTA) ; port RX2_
TX1: TP3.1 U8.1(TXD) ; port TX1
TX2_: TP4.1 U6.3(INB) ; port TX2_
NetJ1_2: J1.2 J4.2 U7.6(CANL)
NetJ1_7: J1.7 R3.2 U7.7(CANH)
NetJ2_2: J2.2 J3.2 U8.6(CANL)
NetJ2_7: J2.7 R4.2 U8.7(CANH)
NetJ3_1: J3.1 R4.1
NetJ4_1: J4.1 R3.1
NetTP2_1: TP2.1 U6.7(INA) U7.4(RXD)
NetTP5_1: TP5.1 U6.6(OUTB) U7.1(TXD)

Not connected (* = marked no-connect by the designer): J1 1 4 5 6 8 9; J2 1 4 5 6 8 9; U7 5(NC); U8 5(NC)

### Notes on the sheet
- Bus Arbitration Logic

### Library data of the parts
C8-C10 C13 = ECPU1C104MA5: as C18 on sheet TIDA-01487A_Power
J1 J2 = 190-009-263R001: CONN DB9 FEMALE R/A SOLDER SMD; Manufacturer: NorComp; SymbolCreator: a07989628; CompType: Connector; Green_Lifecycle: Not Set; Green_REACh: Incomplete
J3 J4 = HB3902U: Header, 2.54mm, 2x1, Gold, TH; Manufacturer: Foxconn; SymbolCreator: a0412235; Pitch_mm: 2.54; Gender: Male; Shrouded: N; Row_Count: 1; Current_A: 3; Voltage_V: 500; Cert_UL: Y
R3 R4 = CRCW0805120RJNEA: RES, 120, 5%, 0.125 W, 0805; Manufacturer: Vishay-Dale; CompType: Resistor; Value: 120; Value_Code: 120R; Tolerance_%: 5; Power_W: 0.125; Value2: 0.125W; VDC_V: 150; TempCo: 200 ppm/C; SizeArea_mm2: 2.5; SizeX_mm: 2; SizeY_mm: 1.25; SizeZ_mm: 1.45; EIA_Code: E24; U/M: EA; AEC Category: Q200
TP1-TP6 = TESTPOINT: TEST POINT.  No entry in BOM.
U6 = ISO7721DR: High Speed, Robust EMC Dual-Channel Digital Isolator, D0008B (SOIC-8); Manufacturer: Texas Instruments; SymbolCreator: Altium; SizeArea_mm2: 29.4; SizeAreaWB_mm2: 55.2; SizeX_mm: 6; SizeY_mm: 4.9; SizeZ_mm: 1.75; CompType: IC; U/M: EA
U7 U8 = TCAN1042HDRQ1: Automotive Fault Protected CAN Transceiver With Flexible Data-Rate, D0008A (SOIC-8); Alternate PartNumber: TCAN1042HDQ1; Manufacturer: Texas Instruments; SymbolCreator: a0411947; SizeArea_mm2: 30.38; SizeAreaWB_mm2: 56.58; SizeX_mm: 4.9; SizeY_mm: 6.2; SizeZ_mm: 1.75; CompType: IC; U/M: EA

## Sheet TIDA-01487A_EVM_Hardware.SchDoc: EVM Hardware
size 431 x 279 mm; Date: Not shown in title block; ApprovedBy: Not shown in title block; CheckedBy: Not shown in title block; Author: Not shown in title block; CompanyName: Not shown in title block; Engineer: Not shown in title block; Organization: Not shown in title block; Address1: Not shown in title block; Address2: Not shown in title block; Address3: Not shown in title block; Address4: Not shown in title block; DocumentNumber: 1; Revision: Use project parameter SCH_Rev; SheetNumber: 5; SheetTotal: 5; PageSetup: Record=PageOptions¦CenterHorizontal=True¦CenterVertical=True¦PrintScale=1.00¦XCorrection=1.00¦YCorrection=1.00¦PrintKind=0¦BorderSize=5000000¦LeftOffset=0¦BottomOffset=0¦Orientation=2¦PaperLength=1000¦PaperWidth=1000¦Scale=100¦PaperSource=15¦PrintQuality=600¦MediaType=1¦DitherType=10¦PaperKind=Letter¦PrintScaleMode=1
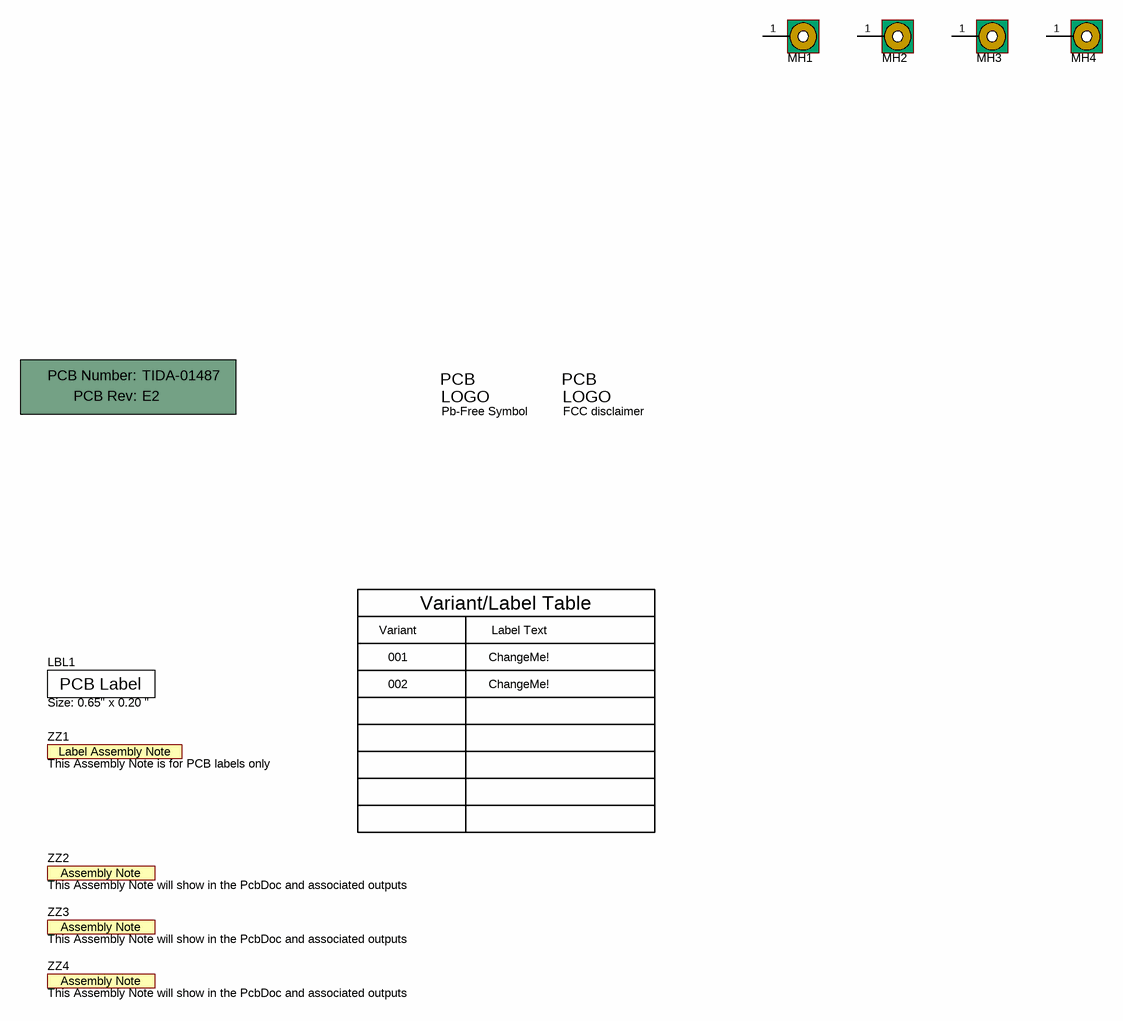
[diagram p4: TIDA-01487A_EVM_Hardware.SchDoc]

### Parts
!PCB1  Printed Circuit Board  (value not drawn)  (mechanical)
LBL1  Size: 0.65" x 0.20 "  [Label_650x200]
Logo2  Pb-Free Symbol  [Pb-Free_Overlay_Medium]  (no BOM)
Logo3  FCC disclaimer  [FCC_disclaimer]  (no BOM)
MH1  MTG_Pads  [MTGP_2-48_PanHead]  (value not drawn)  (no BOM)
MH2  MTG_Pads  [MTGP_2-48_PanHead]  (value not drawn)  (no BOM)
MH3  MTG_Pads  [MTGP_2-48_PanHead]  (value not drawn)  (no BOM)
MH4  MTG_Pads  [MTGP_2-48_PanHead]  (value not drawn)  (no BOM)
ZZ1  This Assembly Note is for PCB labels only  [AssemblyNoteLabel]  (no BOM)
ZZ2  This Assembly Note will show in the PcbDoc and associated outputs  [AssemblyNote]  (no BOM)
ZZ3  This Assembly Note will show in the PcbDoc and associated outputs  [AssemblyNote]  (no BOM)
ZZ4  This Assembly Note will show in the PcbDoc and associated outputs  [AssemblyNote]  (no BOM)

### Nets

Not connected (* = marked no-connect by the designer): MH1 1; MH2 1; MH3 1; MH4 1

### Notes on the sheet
- Variant
- Variant/Label Table
- Label Text
- 001
- 002
- ChangeMe!

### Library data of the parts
!PCB1 = PCB: Manufacturer: Any; PartNumber: TIDA-01487; SymbolCreator: a0412235
LBL1 = THT-14-423-10: Thermal Transfer Printable Labels, 0.650" W x 0.200" H - 10,000 per roll; Manufacturer: Brady; SymbolCreator: a0412235; CompType: Label; Green_Lifecycle: Not Set; Green_REACh: Incomplete
Logo2 = Pb-Free: SymbolCreator: a0412235
Logo3 = FCC_disclaimer: SymbolCreator: a0412235
MH1-MH4 = Mounting Hole (Imperial) with Pads: PCB Mounting Hole; Manufacturer: Any; SymbolCreator: a0412235
ZZ1 = AssemblyNoteLabel: SymbolCreator: a0412235
ZZ2-ZZ4 = AssemblyNote: SymbolCreator: codlsc

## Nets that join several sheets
5V: TIDA-01487A_Power (8 pins), TIDA-01487A_BusArbitrationLogic (12 pins), TIDA-01487A_CanFdInterface (C9.1 C10.1 U6.1 U8.3)
GND: TIDA-01487A_Power (19 pins), TIDA-01487A_BusArbitrationLogic (12 pins), TIDA-01487A_CanFdInterface (6 pins)
ISO_5V: TIDA-01487A_Power (C21.1 R11.2 TP11.1 U12.5), TIDA-01487A_CanFdInterface (C8.1 C13.1 U6.8 U7.3)
ISO_GND: TIDA-01487A_Power (9 pins), TIDA-01487A_CanFdInterface (6 pins)
RX1: TIDA-01487A_BusArbitrationLogic (U1.13 U4.3), TIDA-01487A_CanFdInterface (TP6.1 U8.4)
RX2_: TIDA-01487A_BusArbitrationLogic (U1.1 U4.1), TIDA-01487A_CanFdInterface (TP1.1 U6.2)
TX1: TIDA-01487A_BusArbitrationLogic (U1.3 U2.5 U3.1), TIDA-01487A_CanFdInterface (TP3.1 U8.1)
TX2_: TIDA-01487A_BusArbitrationLogic (U1.11 U2.2 U3.3), TIDA-01487A_CanFdInterface (TP4.1 U6.3)

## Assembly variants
001: not fitted FID1 FID2 FID3 R13 R14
